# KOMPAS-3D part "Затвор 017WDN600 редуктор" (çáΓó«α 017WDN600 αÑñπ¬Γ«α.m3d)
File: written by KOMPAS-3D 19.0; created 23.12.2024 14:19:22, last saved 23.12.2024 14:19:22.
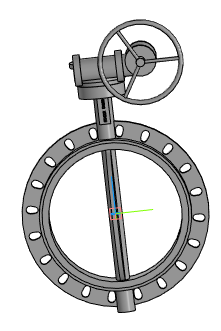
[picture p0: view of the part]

Document properties: Автор: Евгений; Полное имя файла: ..\Затвор 017WDN600 редуктор.a3d

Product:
- Part/product: Затвор 017WDN600 редуктор
    Масса: 279.214

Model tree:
1. Операция без истории:1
